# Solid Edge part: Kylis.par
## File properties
Title: Kylis
Author: DESYS
Comments: .
Template: Intrapresa.par
Last saved by: s.pallini
Revision: 32
Application: Solid Edge
Tipo di contenuto documento: 0
Accuracy: 0,990
Descr rev0: Prima emissione
Descr rev1: .
Descr rev2: .
Document Number: 8046
Revision: 0
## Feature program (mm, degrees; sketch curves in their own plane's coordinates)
lofted protrusion "unnamed LoftedProtrusion 1"
thinwall "Thinwall_8"  Thickness = 10 mm
fillet "Rotondo_33" radius 4
fillet "Rotondo_34" radius 20
sketch for "ExtrudedProtrusion_7" plane through (-140, 0, 0) normal (1, 0, 0) x-axis (0, -1, 0)
extrude "ExtrudedProtrusion_7" add through along +normal  Profile_Plane1_Distance = 140 mm
fillet "Rotondo_35" radius 20
sketch for "unnamed Hole 1" plane through (0, 0, 0) normal (1, 0, 0) x-axis (0, 1, 0)
hole "unnamed Hole 1" through
sketch for "ExtrudedCutout_9" plane through (-140, -1, 0) normal (-1, 0, 0) x-axis (0, -1, 0)
extrude "ExtrudedCutout_9" cut finite 17 along -normal
sketch for "unnamed Protrusion 1" #1 plane through (-140, -1, 0) normal (-1, 0, 0) x-axis (0, -1, 0)
  line (-135.9862, 16.3339) -> (-135.9862, -16.3339)
  line (-120.2198, -12.0657) -> (-135.9862, -16.3339)
  arc centre (-123.4862, 0) radius 12.5 from (-120.2198, 12.0657) to (-120.2198, -12.0657) cw
  line (-120.2198, 12.0657) -> (-135.9862, 16.3339)
sketch for "unnamed Protrusion 1" #2 plane through (-140, -1, 0) normal (-1, 0, 0) x-axis (0, -1, 0)
  line (131.9862, 16.3339) -> (131.9862, -16.3339)
  line (116.2198, -12.0657) -> (131.9862, -16.3339)
  arc centre (119.4862, 0) radius 12.5 from (116.2198, 12.0657) to (116.2198, -12.0657) ccw
  line (116.2198, 12.0657) -> (131.9862, 16.3339)
sketch for "unnamed Protrusion 1" #3 plane through (-140, -1, 0) normal (-1, 0, 0) x-axis (0, -1, 0)
  circle centre (119.4862, 0) radius 5.5
sketch for "unnamed Protrusion 1" #4 plane through (-140, -1, 0) normal (-1, 0, 0) x-axis (0, -1, 0)
  line (-32.1493, -92.5551) -> (27.6298, -92.5551)
  line (16.9169, -78.222) -> (27.6298, -92.5551)
  line (-32.1493, -92.5551) -> (-21.4364, -78.222)
sketch for "unnamed Protrusion 1" #5 plane through (-140, -1, 0) normal (-1, 0, 0) x-axis (0, -1, 0)
  circle centre (-2.2598, -80.3847) radius 5.5
sketch for "unnamed Protrusion 1" #6 plane through (-140, -1, 0) normal (-1, 0, 0) x-axis (0, -1, 0)
  line (-32.1493, 92.5551) -> (27.6298, 92.5551)
  line (16.9169, 78.222) -> (27.6298, 92.5551)
  arc centre (-2.2598, 92.5551) radius 23.9412 from (-21.4364, 78.222) to (16.9169, 78.222) ccw
  line (-32.1493, 92.5551) -> (-21.4364, 78.222)
sketch for "unnamed Protrusion 1" #7 plane through (-140, -1, 0) normal (-1, 0, 0) x-axis (0, -1, 0)
  circle centre (-2.2598, 80.3847) radius 5.5
sketch for "unnamed Protrusion 1" #8 plane through (-140, -1, 0) normal (-1, 0, 0) x-axis (0, -1, 0)
  circle centre (-123.4862, 0) radius 5.5
extrude "unnamed Protrusion 1" add along -normal
fillet "unnamed Round 1"
fillet "Rotondo_38" radius 3
fillet "Rotondo_41" radius 20
fillet "Rotondo_44" radius 20
fillet "Rotondo_46" radius 10
fillet "Rotondo_47" radius 10
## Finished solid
Body 1: solid body, 110 faces, 261 edges, 154 vertices.
  Faces by surface: blend 38, cylinder 31, plane 28, spline 6, offset 4, torus 3
  Edges by curve: intersection 101, line 82, circle 59, ellipse 16, curve on surface 3
Bounding box of the edges (mm; curved faces can reach further): 140.000 x 631.766 x 462.840, from (-140, -315.8828, -231.4198) to (0, 315.8828, 231.4198).
Cylindrical faces by radius (mm): R3 x2, R5 x6, R5.5 x4, R10 x14, R12.5 x2, R23.9412 x2, R25 x1
Toroidal faces (ring radius, tube radius in mm): R22.5 r10 x1, R33.9412 r10 x2
Planar faces by outward normal: +x 2, +y 3, +z 3, -x 6, -y 3, -z 3, oblique 8
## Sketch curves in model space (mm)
arc centre (99.9878, 0, 27.3709) radius 230 from (-130, 0, 25) through (-95.4439, 0, 148.6412) to (0, 0, 234.5)
arc centre (99.9878, 0, -27.3709) radius 230 from (-130, 0, -25) through (-95.4439, 0, -148.6412) to (0, 0, -234.5)
arc centre (318.6619, 49.0248, -34.0278) radius 450 from (0, 310.0445, -215.2) through (-103.5285, 176.9668, -122.8316) to (-130, 20.5376, -14.255)
arc centre (318.6619, -49.0248, 34.0278) radius 450 from (0, -310.0445, 215.2) through (-103.5285, -176.9668, 122.8316) to (-130, -20.5376, 14.255)
arc centre (318.6619, -49.0248, -34.0278) radius 450 from (0, -310.0445, -215.2) through (-103.5285, -176.9668, -122.8316) to (-130, -20.5376, -14.255)
arc centre (318.6619, 49.0248, 34.0278) radius 450 from (0, 310.0445, 215.2) through (-103.5285, 176.9668, 122.8316) to (-130, 20.5376, 14.255)
arc centre (208.8604, -52.8141, 0) radius 340 from (-130, -25, 0) through (-102.4567, -189.495, 0) to (0, -321.1, 0)
arc centre (208.8604, 52.8141, 0) radius 340 from (-130, 25, 0) through (-102.4567, 189.495, 0) to (0, 321.1, 0)
circle centre (-130, 0, 0) radius 25
arc centre (0, 0, 2265.5) radius 2500 from (0, -310.0445, -215.2) through (0, 0, -234.5) to (0, 310.0445, -215.2)
arc centre (0, -1778.9, 0) radius 2100 from (0, 310.0445, 215.2) through (0, 321.1, 0) to (0, 310.0445, -215.2)
arc centre (0, 0, -2265.5) radius 2500 from (0, -310.0445, 215.2) through (0, 0, 234.5) to (0, 310.0445, 215.2)
arc centre (0, 1778.9, 0) radius 2100 from (0, -310.0445, 215.2) through (0, -321.1, 0) to (0, -310.0445, -215.2)
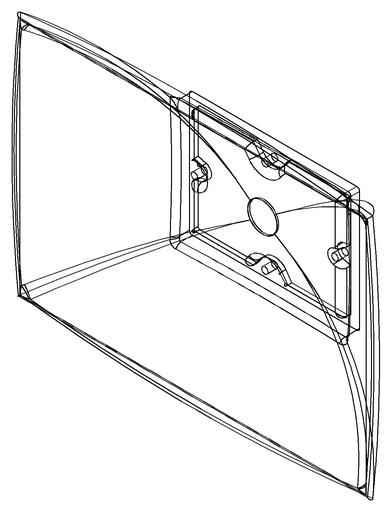
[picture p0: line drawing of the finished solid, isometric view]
